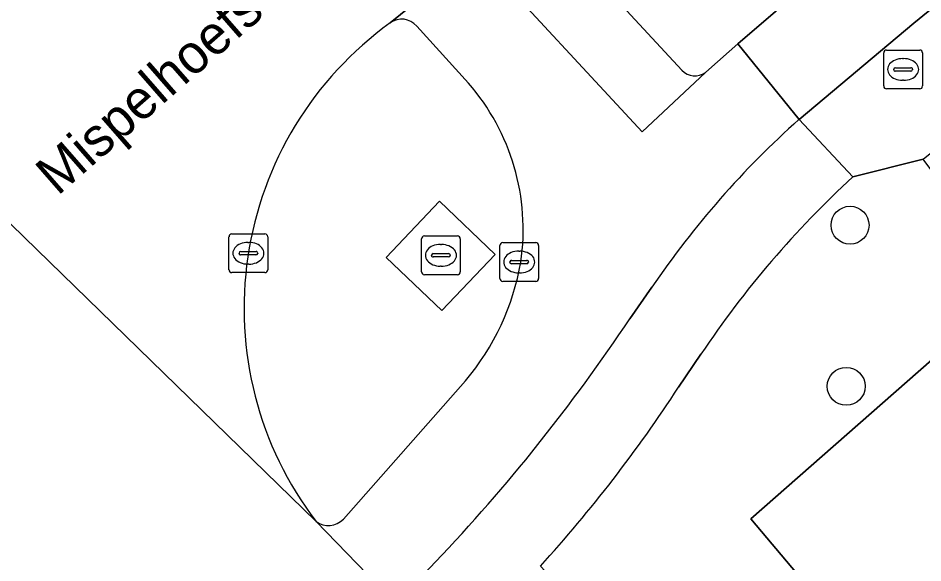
# Model space of a CAD drawing. Extents: x 156141 to 158132, y 385651 to 388333.
# Drawn here: x 156953.98 to 156977.31, y 387257.6 to 387271.63 of the extents above; entities that cross this region are included whole.
import ezdxf

# ---------------------------------------------------------------- set-up
doc = ezdxf.new("R2010")
doc.units = 0
for name, color, linetype in [('IMGEO_Berm_groen', 7, 'Continuous'), ('IMGEO_Boom', 7, 'Continuous'), ('IMGEO_Brandkraan', 7, 'Continuous'), ('IMGEO_Erf', 7, 'Continuous'), ('IMGEO_Fietspad_gesloten', 7, 'Continuous'), ('IMGEO_Groenvoorziening', 7, 'Continuous'), ('IMGEO_Kolk', 7, 'Continuous'), ('IMGEO_Openbare_ruimte_label', 7, 'Continuous'), ('IMGEO_Rijbaan_lokaal_gesloten', 7, 'Continuous'), ('IMGEO_Rioolput', 7, 'Continuous'), ('IMGEO_Verkeerseiland_groen', 7, 'Continuous'), ('IMGEO_Verkeerseiland_open', 7, 'Continuous'), ('IMGEO_Voetpad_open', 7, 'Continuous')]:
    doc.layers.add(name, color=color, linetype=linetype)

msp = doc.modelspace()

# ---------------------------------------------------------------- linework, layer by layer
at = {"layer": 'IMGEO_Berm_groen'}
for points in [[(156971.699, 387270.231), (156971.787, 387270.313), (156972.534, 387270.974), (156975.448, 387273.477), (156991.426, 387286.507)], [(156967.585, 387274.079), (156971.094, 387270.292)]]:
    msp.add_lwpolyline(points, dxfattribs=at)
msp.add_arc((156971.431, 387270.604), 0.459, 222.7795, 305.7056, dxfattribs=at)
at = {"layer": 'IMGEO_Boom'}
for centre in [(156975.428, 387266.298), (156975.329, 387262.147)]:
    msp.add_circle(centre, 0.489, dxfattribs=at)
at = {"layer": 'IMGEO_Brandkraan'}
for p, q in [((156964.379, 387265.096), (156964.379, 387265.948)), ((156964.454, 387266.022), (156965.306, 387266.022)), ((156965.38, 387265.948), (156965.38, 387265.096)), ((156964.867, 387265.802), (156964.892, 387265.802)), ((156964.638, 387265.516), (156964.638, 387265.528)), ((156964.681, 387265.565), (156965.079, 387265.565)), ((156965.122, 387265.528), (156965.122, 387265.516)), ((156965.076, 387265.479), (156964.678, 387265.479)), ((156965.306, 387265.022), (156964.454, 387265.022)), ((156964.89, 387265.242), (156964.865, 387265.242))]:
    msp.add_line(p, q, dxfattribs=at)
for points in [[(156964.379, 387265.096), (156964.379, 387265.948)], [(156964.454, 387266.022), (156965.306, 387266.022)], [(156965.38, 387265.948), (156965.38, 387265.096)], [(156965.306, 387265.022), (156964.454, 387265.022)]]:
    msp.add_lwpolyline(points, dxfattribs=at)
for centre, radius, start, end in [((156964.456, 387265.946), 0.0765, 91.552, 178.448), ((156964.456, 387265.946), 0.0765, 91.552, 178.448), ((156965.304, 387265.946), 0.0765, 1.552, 88.448), ((156965.304, 387265.946), 0.0765, 1.552, 88.448), ((156964.678, 387265.525), 0.0403, 85.8775, 175.7526), ((156964.675, 387265.515), 0.0366, 178.938, 274.7102), ((156965.079, 387265.522), 0.043, 264.8664, 352.4533), ((156965.083, 387265.527), 0.0386, 1.7309, 96.639), ((156964.456, 387265.098), 0.0765, 181.552, 268.448), ((156964.456, 387265.098), 0.0765, 181.552, 268.448), ((156965.304, 387265.098), 0.0765, 271.552, 358.448), ((156965.304, 387265.098), 0.0765, 271.552, 358.448)]:
    msp.add_arc(centre, radius, start, end, dxfattribs=at)
for centre, major_axis, ratio, start_param, end_param in [((156964.866, 387265.522), (-0.387, 0.002), 0.722429, 4.712389, 7.853982), ((156964.891, 387265.522), (-0.39, 0.002), 0.717154, 1.570796, 4.712389)]:
    msp.add_ellipse(centre, major_axis=major_axis, ratio=ratio, start_param=start_param, end_param=end_param, dxfattribs=at)
at = {"layer": 'IMGEO_Erf'}
msp.add_lwpolyline([(156997.335, 387280.22), (156972.874, 387258.731), (156991.615, 387236.498), (157008.894, 387219.22), (157018.971, 387209.107), (157019.161, 387208.917), (157017.59, 387207.429), (157020.313, 387201.752), (157031.114, 387190.532), (157034.448, 387193.714), (157034.641, 387193.656), (157037.049, 387195.925), (157039.113, 387193.735), (157036.705, 387191.466), (157050.601, 387176.491), (157048.291, 387174.308), (157048.528, 387174.052), (157052.568, 387169.626), (157055.477, 387172.297), (157057.621, 387174.266), (157112.914, 387223.48), (157031.438, 387308.365)], dxfattribs=at)
at = {"layer": 'IMGEO_Fietspad_gesloten'}
for points in [[(157032.24, 387319.54), (157031.642, 387319.061), (157031.044, 387318.581), (157028.612, 387316.704), (157025.748, 387314.495), (157022.245, 387311.639), (157020.931, 387310.567), (157000, 387293.499), (156999.323, 387292.947), (156991.426, 387286.507), (156975.448, 387273.477), (156972.534, 387270.974), (156974.112, 387269.023), (156977.074, 387271.5), (156993.494, 387284.877), (157000, 387290.177), (157000.705, 387290.751), (157022.872, 387308.809), (157024.049, 387309.768), (157027.571, 387312.603), (157030.022, 387314.573), (157032.484, 387316.526), (157035.491, 387318.9)], [(156974.112, 387269.023), (156972.534, 387270.974), (156971.787, 387270.313), (156971.699, 387270.231), (156970.072, 387268.708), (156965.798, 387273.316), (156963.569, 387271.508)], [(156964.257, 387271.429), (156965.588, 387269.958)], [(156969.749, 387263.887), (156970.32, 387264.698)], [(156965.516, 387262.291), (156962.366, 387258.727)], [(156961.662, 387258.661), (156964.035, 387256.218)], [(156964.065, 387256.908), (156964.742, 387257.624)]]:
    msp.add_lwpolyline(points, dxfattribs=at)
for centre, radius, start, end in [((156963.87, 387271.096), 0.51, 40.7215, 126.1778), ((156961.289, 387266.197), 5.712, 351.4299, 41.1782), ((156989.737, 387251.499), 23.479, 131.7209, 145.7929), ((156960.651, 387266.412), 6.375, 319.733, 350.377), ((156930.855, 387289.848), 46.763, 316.4409, 326.2774), ((156961.977, 387259.089), 0.532, 233.6624, 317.0493)]:
    msp.add_arc(centre, radius, start, end, dxfattribs=at)
at = {"layer": 'IMGEO_Groenvoorziening'}
msp.add_lwpolyline([(156995.388, 387282.622), (156995.376, 387282.637), (156993.494, 387284.877), (156977.074, 387271.5), (156974.112, 387269.023), (156975.501, 387267.541), (156977.315, 387267.998)], close=True, dxfattribs=at)
for points in [[(156972.874, 387258.731), (156997.335, 387280.22), (156997.381, 387280.263), (156996.982, 387280.734), (156978.913, 387265.86), (156977.315, 387267.998), (156975.501, 387267.541)], [(156971.584, 387262.972), (156971.004, 387262.123)], [(156967.444, 387257.514), (156967.793, 387257.148), (156971.51, 387253.257), (156972.917, 387254.49), (156976.669, 387250.523), (156975.389, 387249.304), (156973.004, 387247.06), (156981.096, 387238.787), (156983.277, 387236.557), (156983.14, 387236.417), (156983.736, 387235.751), (156994.606, 387225.243), (156996.699, 387223.238), (156998.437, 387221.508), (156999.173, 387220.753), (157000, 387219.913), (157001.467, 387218.423), (157008.894, 387219.22), (156991.615, 387236.498), (156972.874, 387258.731)]]:
    msp.add_lwpolyline(points, dxfattribs=at)
for centre, radius, start, end in [((156992.409, 387249.082), 25.032, 132.4894, 146.2976), ((156940.669, 387281.875), 36.199, 317.7035, 326.9314)]:
    msp.add_arc(centre, radius, start, end, dxfattribs=at)
at = {"layer": 'IMGEO_Kolk'}
for p, q in [((156959.416, 387265.15), (156959.416, 387266.002)), ((156959.491, 387266.076), (156960.343, 387266.076)), ((156960.417, 387266.002), (156960.417, 387265.15)), ((156959.904, 387265.856), (156959.929, 387265.856)), ((156966.398, 387264.924), (156966.398, 387265.776)), ((156966.473, 387265.85), (156967.325, 387265.85)), ((156967.399, 387265.776), (156967.399, 387264.924)), ((156959.675, 387265.57), (156959.675, 387265.582)), ((156960.113, 387265.533), (156959.715, 387265.533)), ((156959.718, 387265.619), (156960.116, 387265.619)), ((156960.159, 387265.582), (156960.159, 387265.57)), ((156966.886, 387265.63), (156966.911, 387265.63)), ((156959.927, 387265.296), (156959.902, 387265.296)), ((156966.657, 387265.344), (156966.657, 387265.356)), ((156967.095, 387265.307), (156966.697, 387265.307)), ((156966.7, 387265.393), (156967.098, 387265.393)), ((156967.141, 387265.356), (156967.141, 387265.344)), ((156960.343, 387265.076), (156959.491, 387265.076)), ((156966.909, 387265.07), (156966.884, 387265.07)), ((156967.325, 387264.85), (156966.473, 387264.85))]:
    msp.add_line(p, q, dxfattribs=at)
for points in [[(156959.416, 387265.15), (156959.416, 387266.002)], [(156959.491, 387266.076), (156960.343, 387266.076)], [(156960.417, 387266.002), (156960.417, 387265.15)], [(156966.398, 387264.924), (156966.398, 387265.776)], [(156966.473, 387265.85), (156967.325, 387265.85)], [(156967.399, 387265.776), (156967.399, 387264.924)], [(156960.343, 387265.076), (156959.491, 387265.076)], [(156967.325, 387264.85), (156966.473, 387264.85)]]:
    msp.add_lwpolyline(points, dxfattribs=at)
for centre, radius, start, end in [((156959.493, 387266), 0.0765, 91.552, 178.448), ((156959.493, 387266), 0.0765, 91.552, 178.448), ((156960.341, 387266), 0.0765, 1.552, 88.448), ((156960.341, 387266), 0.0765, 1.552, 88.448), ((156966.475, 387265.774), 0.0765, 91.552, 178.448), ((156966.475, 387265.774), 0.0765, 91.552, 178.448), ((156967.323, 387265.774), 0.0765, 1.552, 88.448), ((156967.323, 387265.774), 0.0765, 1.552, 88.448), ((156959.715, 387265.579), 0.0403, 85.8775, 175.7526), ((156959.712, 387265.569), 0.0366, 178.938, 274.7102), ((156960.116, 387265.576), 0.043, 264.8664, 352.4533), ((156960.12, 387265.581), 0.0386, 1.7309, 96.639), ((156966.697, 387265.353), 0.0403, 85.8775, 175.7526), ((156966.694, 387265.343), 0.0366, 178.938, 274.7102), ((156967.098, 387265.35), 0.043, 264.8664, 352.4533), ((156967.102, 387265.355), 0.0386, 1.7309, 96.639), ((156959.493, 387265.152), 0.0765, 181.552, 268.448), ((156959.493, 387265.152), 0.0765, 181.552, 268.448), ((156960.341, 387265.152), 0.0765, 271.552, 358.448), ((156960.341, 387265.152), 0.0765, 271.552, 358.448), ((156966.475, 387264.926), 0.0765, 181.552, 268.448), ((156966.475, 387264.926), 0.0765, 181.552, 268.448), ((156967.323, 387264.926), 0.0765, 271.552, 358.448), ((156967.323, 387264.926), 0.0765, 271.552, 358.448)]:
    msp.add_arc(centre, radius, start, end, dxfattribs=at)
for centre, major_axis, ratio, start_param, end_param in [((156959.903, 387265.576), (-0.387, 0.002), 0.722429, 4.712389, 7.853982), ((156959.928, 387265.576), (-0.39, 0.002), 0.717154, 1.570796, 4.712389), ((156966.885, 387265.35), (-0.387, 0.002), 0.722429, 4.712389, 7.853982), ((156966.91, 387265.35), (-0.39, 0.002), 0.717154, 1.570796, 4.712389)]:
    msp.add_ellipse(centre, major_axis=major_axis, ratio=ratio, start_param=start_param, end_param=end_param, dxfattribs=at)
at = {"layer": 'IMGEO_Rijbaan_lokaal_gesloten'}
for points in [[(156963.569, 387271.508), (156965.798, 387273.316), (156967.593, 387274.767), (156972.195, 387278.427), (156972.416, 387278.172), (156979.146, 387283.613)], [(156958.491, 387256.07), (156958.567, 387255.991), (156960.84, 387253.61), (156962.022, 387252.337), (156965.158, 387255.083), (156964.035, 387256.218), (156961.662, 387258.661), (156943.639, 387276.201)], [(156944.192, 387275.84), (156943.639, 387276.201), (156961.662, 387258.661)]]:
    msp.add_lwpolyline(points, dxfattribs=at)
msp.add_arc((156968.862, 387264.157), 9.058, 125.7557, 217.3577, dxfattribs=at)
at = {"layer": 'IMGEO_Rioolput'}
for p, q in [((156976.296, 387269.885), (156976.296, 387270.737)), ((156976.371, 387270.811), (156977.223, 387270.811)), ((156977.297, 387270.737), (156977.297, 387269.885)), ((156976.784, 387270.591), (156976.809, 387270.591)), ((156976.555, 387270.305), (156976.555, 387270.317)), ((156976.993, 387270.268), (156976.595, 387270.268)), ((156976.598, 387270.354), (156976.996, 387270.354)), ((156977.039, 387270.317), (156977.039, 387270.305)), ((156976.807, 387270.031), (156976.782, 387270.031)), ((156977.223, 387269.811), (156976.371, 387269.811))]:
    msp.add_line(p, q, dxfattribs=at)
for points in [[(156976.296, 387269.885), (156976.296, 387270.737)], [(156976.371, 387270.811), (156977.223, 387270.811)], [(156977.297, 387270.737), (156977.297, 387269.885)], [(156977.223, 387269.811), (156976.371, 387269.811)]]:
    msp.add_lwpolyline(points, dxfattribs=at)
for centre, radius, start, end in [((156976.373, 387270.735), 0.0765, 91.552, 178.448), ((156976.373, 387270.735), 0.0765, 91.552, 178.448), ((156977.221, 387270.735), 0.0765, 1.552, 88.448), ((156977.221, 387270.735), 0.0765, 1.552, 88.448), ((156976.595, 387270.314), 0.0403, 85.8775, 175.7526), ((156976.592, 387270.304), 0.0366, 178.938, 274.7102), ((156976.996, 387270.311), 0.043, 264.8664, 352.4533), ((156977, 387270.316), 0.0386, 1.7309, 96.639), ((156976.373, 387269.887), 0.0765, 181.552, 268.448), ((156976.373, 387269.887), 0.0765, 181.552, 268.448), ((156977.221, 387269.887), 0.0765, 271.552, 358.448), ((156977.221, 387269.887), 0.0765, 271.552, 358.448)]:
    msp.add_arc(centre, radius, start, end, dxfattribs=at)
for centre, major_axis, ratio, start_param, end_param in [((156976.783, 387270.311), (-0.387, 0.002), 0.722429, 4.712389, 7.853982), ((156976.808, 387270.311), (-0.39, 0.002), 0.717154, 1.570796, 4.712389)]:
    msp.add_ellipse(centre, major_axis=major_axis, ratio=ratio, start_param=start_param, end_param=end_param, dxfattribs=at)
at = {"layer": 'IMGEO_Verkeerseiland_groen'}
for points in [[(156965.588, 387269.958), (156964.257, 387271.429)], [(156962.366, 387258.727), (156965.516, 387262.291)]]:
    msp.add_lwpolyline(points, dxfattribs=at)
msp.add_lwpolyline([(156964.84, 387266.917), (156966.278, 387265.541), (156964.907, 387264.1), (156963.465, 387265.47)], close=True, dxfattribs=at)
for centre, radius, start, end in [((156963.87, 387271.096), 0.51, 40.7215, 126.1778), ((156968.862, 387264.157), 9.058, 125.7557, 217.3577), ((156961.289, 387266.197), 5.712, 351.4299, 41.1782), ((156960.651, 387266.412), 6.375, 319.733, 350.377), ((156961.977, 387259.089), 0.532, 233.6624, 317.0493)]:
    msp.add_arc(centre, radius, start, end, dxfattribs=at)
at = {"layer": 'IMGEO_Verkeerseiland_open'}
msp.add_lwpolyline([(156966.278, 387265.541), (156964.84, 387266.917), (156963.465, 387265.47), (156964.907, 387264.1)], close=True, dxfattribs=at)
at = {"layer": 'IMGEO_Voetpad_open'}
for points in [[(156967.593, 387274.767), (156965.798, 387273.316), (156970.072, 387268.708), (156971.699, 387270.231)], [(156971.094, 387270.292), (156967.585, 387274.079)], [(156975.501, 387267.541), (156974.112, 387269.023)], [(156970.32, 387264.698), (156969.749, 387263.887)], [(156971.004, 387262.123), (156971.584, 387262.972)], [(156964.742, 387257.624), (156964.065, 387256.908)]]:
    msp.add_lwpolyline(points, dxfattribs=at)
for centre, radius, start, end in [((156971.431, 387270.604), 0.459, 222.7795, 305.7056), ((156989.737, 387251.499), 23.479, 131.7209, 145.7929), ((156992.409, 387249.082), 25.032, 132.4894, 146.2976), ((156930.855, 387289.848), 46.763, 316.4409, 326.2774), ((156940.669, 387281.875), 36.199, 317.7035, 326.9314)]:
    msp.add_arc(centre, radius, start, end, dxfattribs=at)

# ---------------------------------------------------------------- texts
at = {"layer": 'IMGEO_Openbare_ruimte_label'}
msp.add_text('Mispelhoefstraat', height=1, rotation=41.1482, dxfattribs=at).set_placement((156954.998, 387267.037))

doc.saveas('drawing.dxf')
